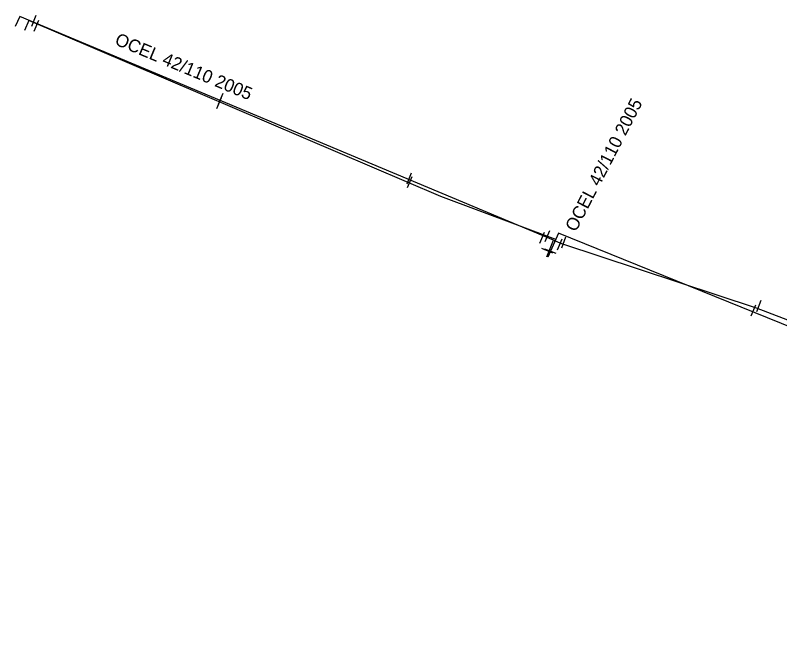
# Model space of a CAD drawing. Extents: x -642943 to -623314, y -1138561 to -1113539.
# Drawn here: x -642573.12 to -642528.23, y -1114679.06 to -1114641.96 of the extents above; entities that cross this region are included whole.
import ezdxf

# ---------------------------------------------------------------- set-up
doc = ezdxf.new("R2010")
doc.units = 0
for name, color, linetype in [('horkovod dimenze', 7, 'Continuous'), ('horkovod předisol', 7, 'Continuous'), ('horkovod sváry', 7, 'Continuous'), ('horkovod trasa', 7, 'Continuous'), ('horkovod zrušený', 7, 'Continuous')]:
    doc.layers.add(name, color=color, linetype=linetype)

# ---------------------------------------------------------------- blocks, each defined once
blk = doc.blocks.new('SPH')
at = {"layer": 'horkovod sváry'}
blk.add_line((0, -0.035), (0, 0.035), dxfattribs=at)

msp = doc.modelspace()

# ---------------------------------------------------------------- linework, layer by layer
at = {"layer": 'horkovod předisol'}
msp.add_line((-642541.905, -1114656.145), (-642541.512, -1114655.175), dxfattribs=at)
for points in [[(-642541.512, -1114655.175), (-642572.855, -1114642.035), (-642573.117, -1114642.616)], [(-642541.512, -1114655.175), (-642541.044, -1114655.374), (-642529.609, -1114659.156), (-642518.109, -1114663.552), (-642506.527, -1114668.312)]]:
    msp.add_lwpolyline(points, dxfattribs=at)
at = {"layer": 'horkovod trasa'}
msp.add_line((-642541.905, -1114656.145), (-642541.512, -1114655.175), dxfattribs=at)
for points in [[(-642541.512, -1114655.175), (-642572.855, -1114642.035), (-642573.117, -1114642.616)], [(-642541.512, -1114655.175), (-642541.044, -1114655.374), (-642529.609, -1114659.156), (-642518.109, -1114663.552), (-642506.527, -1114668.312)]]:
    msp.add_lwpolyline(points, dxfattribs=at)
at = {"layer": 'horkovod zrušený'}
for points in [[(-642541.386, -1114655.138), (-642548.13, -1114652.609), (-642572.324, -1114642.257), (-642572.582, -1114642.842)], [(-642481.964, -1114679.064), (-642507.4, -1114670.368), (-642508.906, -1114669.737), (-642508.224, -1114668.132), (-642541.216, -1114654.753), (-642541.842, -1114656.168)]]:
    msp.add_lwpolyline(points, dxfattribs=at)

# ---------------------------------------------------------------- block references
at = {"layer": 'horkovod sváry'}
for p, xscale, yscale, rotation in [((-642572.022, -1114642.28), 10.00000295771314, 10.00000295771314, -22.036250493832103), ((-642571.872, -1114642.57), 10.000009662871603, 10.000009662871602, -21.748694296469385), ((-642561.042, -1114646.86), 10.000009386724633, 10.000009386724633, -22.681599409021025), ((-642561.142, -1114647.11), 10.000016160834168, 10.00001616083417, -22.52898726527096), ((-642549.982, -1114651.54), 10.0000067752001, 10.000006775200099, -22.57407717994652), ((-642549.952, -1114651.76), 10.000019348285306, 10.000019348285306, -22.53042393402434), ((-642541.862, -1114654.92), 10.000013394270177, 10.000013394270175, -23.167971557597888), ((-642542.182, -1114655.02), 10.000019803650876, 10.000019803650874, -23.634266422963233), ((-642540.922, -1114655.32), 9.999984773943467, 9.999984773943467, 159.56243077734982), ((-642541.162, -1114655.44), 9.9999901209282, 9.999990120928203, 158.49263806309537), ((-642541.882, -1114655.8), 10.000006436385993, 10.000006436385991, 68.36902336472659), ((-642541.692, -1114655.82), 10.000018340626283, 10.000018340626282, 68.91536661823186), ((-642529.772, -1114659.29), 9.999956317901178, 9.999956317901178, -23.58346955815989), ((-642529.442, -1114659.03), 9.99998428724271, 9.999984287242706, -21.420508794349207)]:
    msp.add_blockref('SPH', p, dxfattribs=dict(at, xscale=xscale, yscale=yscale, rotation=rotation))

# ---------------------------------------------------------------- texts
at = {"layer": 'horkovod dimenze'}
for rotation, p in [(337.3579, (-642567.326, -1114643.654)), (62.7447, (-642540.202, -1114654.729))]:
    msp.add_text('OCEL 42/110 2005', height=0.75, rotation=rotation, dxfattribs=at).set_placement(p)

doc.saveas('drawing.dxf')
